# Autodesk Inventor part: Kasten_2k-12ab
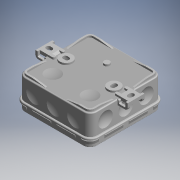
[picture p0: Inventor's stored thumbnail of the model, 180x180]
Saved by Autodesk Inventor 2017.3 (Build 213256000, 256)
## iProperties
Part Number: Kasten_2k-12ab
Material: Generic
Catalog Web Link: www.cadenas.de
Description: Kasten_2k-12ab-Rote Reihe
Vendor: SPELSBERG
Document SubType Name: Modeling
Designer: partserver
Manufacturer: SPELSBERG
Mass: 30.8757 g
Surface Area: 386.027 cm^2
Volume: 30.8757 cm^3
Density: 1 g/cm^3
Appearance: PSOLRGB-215-215-215
Category: PARTsolutions
Company: SPELSBERG
Title: Kasten_2k-12ab
Author: Cadenas PARTsolutions
Comments: Rote Reihe
PSOL_IDENT_0: {$CADENAS_DATA\23d-libs\spelsberg\pool\verbindungsdosen\parts\kasten_2k_12_ab.prj},176 {VTYP=3D},{NB=
PSOL_IDENT_1: Kasten_2k-12ab},{LINA=Kasten_2k-12ab},{NN=Kasten_2k-12ab},{DATE=27.03.2020 09:10:35},{GEOMDATE=05.01
PSOL_IDENT_2: .2015 11:33:00},{VERSION=},{LINEID=10},{WBVAR=},{WBNUMERIC=}  {NB=Kasten_2k-12ab},{LINA=Kasten_2k-12
PSOL_IDENT_3: ab},{KT=DUMMY},{CNSORDERNO=Kasten_2k-12ab}
NB: Kasten_2k-12ab
NN: Kasten_2k-12ab
NT: Rote Reihe
NBSYN: $CNSORDERNO.
LINA: Kasten_2k-12ab
CATALOG: Spelsberg
CNSORDERNO: Kasten_2k-12ab
SUPPLIER: SPELSBERG
ARTICLENO: Kasten_2k-12ab
BOMINFO: Kasten_2k-12ab
CREATOR: CADENAS GmbH
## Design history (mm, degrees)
sketch "Sketch_1"
  geometry: L1 (-40.5, 7.5)-(-40.5, 5); L2 (-40.5, 5)-(-41.411, 1.6); L3 (-41.411, 1.6)-(-40.5, 1.6); L4 (-40.5, 1.6)-(-40.5, 0); L5 (-40.5, 0)-(-42.5, 0); L6 (-42.5, 0)-(-42.5, -1); L7 (-41.5, -2)-(-40.5, -2); L8 (-40.5, -2)-(-40.5, -24.5); L9 (-39.5, -25.5)-(39.5, -25.5); L10 (40.5, -24.5)-(40.5, -2); L11 (40.5, -2)-(41.5, -2); L12 (42.5, -1)-(42.5, 0); L13 (42.5, 0)-(40.5, 0); L14 (40.5, 0)-(40.5, 1.6); L15 (40.5, 1.6)-(41.411, 1.6); L16 (41.411, 1.6)-(40.5, 5); L17 (40.5, 5)-(40.5, 7.5); L18 (40, 8)-(-40, 8); A1 r 0.5 centre (-40, 7.5) between (-40, 8) and (-40.5, 7.5); A2 r 1 centre (-41.5, -1) between (-42.5, -1) and (-41.5, -2); A3 r 1 centre (-39.5, -24.5) between (-40.5, -24.5) and (-39.5, -25.5); A4 r 1 centre (39.5, -24.5) between (39.5, -25.5) and (40.5, -24.5); A5 r 1 centre (41.5, -1) between (41.5, -2) and (42.5, -1); A6 r 0.5 centre (40, 7.5) between (40.5, 7.5) and (40, 8)
  constraints: 36 end point, 12 point on circle, 6 centre point
extrude "Extrusion1" join sketch "Sketch_1" stored distance "d0" = 66; taper "d1" = 0 deg
sketch "Sketch_2"
  geometry: L1 (42.5, 0)-(40.5, 0); L2 (40.5, 0)-(40.5, 1.6); L3 (40.5, 1.6)-(41.411, 1.6); L4 (41.411, 1.6)-(40.5, 5); L5 (40.5, 5)-(40.5, 7.499); L6 (39.999, 8)-(-39.999, 8); L7 (-40.5, 7.499)-(-40.5, 5); L8 (-40.5, 5)-(-41.411, 1.6); L9 (-41.411, 1.6)-(-40.5, 1.6); L10 (-40.5, 1.6)-(-40.5, 0); L11 (-40.5, 0)-(-42.5, 0); L12 (-42.5, 0)-(-42.5, -0.999); L13 (-41.499, -2)-(-40.5, -2); L14 (-40.5, -2)-(-40.5, -24.5); L15 (-39.5, -25.5)-(39.5, -25.5); L16 (40.5, -24.5)-(40.5, -2); L17 (40.5, -2)-(41.499, -2); L18 (42.5, -0.999)-(42.5, 0); A1 r 0.501 centre (39.999, 7.499) between (40.5, 7.499) and (39.999, 8); A2 r 0.501 centre (-39.999, 7.499) between (-39.999, 8) and (-40.5, 7.499); A3 r 1.001 centre (-41.499, -0.999) between (-42.5, -0.999) and (-41.499, -2); A4 r 1 centre (-39.5, -24.5) between (-40.5, -24.5) and (-39.5, -25.5); A5 r 1 centre (39.5, -24.5) between (39.5, -25.5) and (40.5, -24.5); A6 r 1.001 centre (41.499, -0.999) between (41.499, -2) and (42.5, -0.999)
  constraints: 36 end point, 12 point on circle, 6 centre point
extrude "Extrusion2" join sketch "Sketch_2" stored distance "d2" = 66; taper "d3" = 0 deg
sketch "Sketch_7"
  geometry: L1 (-39.5, 10)-(-39.5, 8); L2 (-39, 7.5)-(-39, -24); L3 (-39, -24)-(39, -24); L4 (39, -24)-(39, 7.5); L5 (39.5, 8)-(39.5, 10); L6 (39.5, 10)-(-39.5, 10); A1 r 0.5 centre (-39.5, 7.5) between (-39, 7.5) and (-39.5, 8); A2 r 0.5 centre (39.5, 7.5) between (39.5, 8) and (39, 7.5)
  constraints: 12 end point, 4 point on circle, 2 centre point
extrude "Extrusion3" cut sketch "Sketch_7" stored distance "d4" = 66; taper "d5" = 0 deg
sketch "Sketch_8"
  geometry: L1 (39.5, 8)-(39.5, 10); L2 (39.5, 10)-(-39.5, 10); L3 (-39.5, 10)-(-39.5, 8); L4 (-39, 7.5)-(-39, -24); L5 (-39, -24)-(39, -24); L6 (39, -24)-(39, 7.5); A1 r 0.5 centre (-39.5, 7.5) between (-39, 7.5) and (-39.5, 8); A2 r 0.5 centre (39.5, 7.5) between (39.5, 8) and (39, 7.5)
  constraints: 12 end point, 4 point on circle, 2 centre point
extrude "Extrusion4" cut sketch "Sketch_8" stored distance "d6" = 66; taper "d7" = 0 deg
sketch "Sketch_3"
  geometry: L1 (25.5, 33)-(-8, 33); L2 (24, 33)-(24, 39); L3 (24, 39)-(-7.5, 39); L4 (-8, 39.5)-(-8, 40); L5 (-7.5, 40.5)-(-5, 40.5); L6 (-5, 40.5)-(-1.6, 41.411); L7 (-1.6, 41.411)-(-1.6, 40.5); L8 (-1.6, 40.5)-(0, 40.5); L9 (0, 40.5)-(0, 42.5); L10 (0, 42.5)-(1, 42.5); L11 (2, 41.5)-(2, 40.5); L12 (2, 40.5)-(24.5, 40.5); L13 (25.5, 39.5)-(25.5, 33); L14 (25.5, 33)-(24, 33); A1 r 0.5 centre (-7.5, 39.5) between (-8, 39.5) and (-7.5, 39); A2 r 0.5 centre (-7.5, 40) between (-7.5, 40.5) and (-8, 40); A3 r 1 centre (1, 41.5) between (2, 41.5) and (1, 42.5); A4 r 1 centre (24.5, 39.5) between (25.5, 39.5) and (24.5, 40.5)
  constraints: 28 end point, 8 point on circle, 4 centre point
revolve "Revolution1" sketch "Sketch_3" stored, may be unused: angle "d8" = 90 deg
sketch "Sketch_4"
  geometry: L1 (-8, -33)-(25.5, -33); L2 (25.5, -33)-(25.5, -39.5); L3 (24.5, -40.5)-(2, -40.5); L4 (2, -40.5)-(2, -41.5); L5 (1, -42.5)-(0, -42.5); L6 (0, -42.5)-(0, -40.5); L7 (0, -40.5)-(-1.6, -40.5); L8 (-1.6, -40.5)-(-1.6, -41.411); L9 (-1.6, -41.411)-(-5, -40.5); L10 (-5, -40.5)-(-7.5, -40.5); L11 (-8, -40)-(-8, -39.5); L12 (-7.5, -39)-(24, -39); L13 (24, -39)-(24, -33); L14 (24, -33)-(25.5, -33); A1 r 1 centre (24.5, -39.5) between (24.5, -40.5) and (25.5, -39.5); A2 r 1 centre (1, -41.5) between (1, -42.5) and (2, -41.5); A3 r 0.5 centre (-7.5, -40) between (-8, -40) and (-7.5, -40.5); A4 r 0.5 centre (-7.5, -39.5) between (-7.5, -39) and (-8, -39.5)
  constraints: 28 end point, 8 point on circle, 4 centre point
revolve "Revolution2" sketch "Sketch_4" stored, may be unused: angle "d9" = 90 deg
sketch "Sketch_5"
  geometry: L1 (25.5, 33)-(-8, 33); L2 (24, 33)-(24, 39); L3 (24, 39)-(-7.5, 39); L4 (-8, 39.5)-(-8, 40); L5 (-7.5, 40.5)-(-5, 40.5); L6 (-5, 40.5)-(-1.6, 41.411); L7 (-1.6, 41.411)-(-1.6, 40.5); L8 (-1.6, 40.5)-(0, 40.5); L9 (0, 40.5)-(0, 42.5); L10 (0, 42.5)-(1, 42.5); L11 (2, 41.5)-(2, 40.5); L12 (2, 40.5)-(24.5, 40.5); L13 (25.5, 39.5)-(25.5, 33); L14 (25.5, 33)-(24, 33); A1 r 0.5 centre (-7.5, 39.5) between (-8, 39.5) and (-7.5, 39); A2 r 0.5 centre (-7.5, 40) between (-7.5, 40.5) and (-8, 40); A3 r 1 centre (1, 41.5) between (2, 41.5) and (1, 42.5); A4 r 1 centre (24.5, 39.5) between (25.5, 39.5) and (24.5, 40.5)
  constraints: 28 end point, 8 point on circle, 4 centre point
revolve "Revolution3" sketch "Sketch_5" stored, may be unused: angle "d10" = 90 deg
sketch "Sketch_6"
  geometry: L1 (-8, -33)-(25.5, -33); L2 (25.5, -33)-(25.5, -39.5); L3 (24.5, -40.5)-(2, -40.5); L4 (2, -40.5)-(2, -41.5); L5 (1, -42.5)-(0, -42.5); L6 (0, -42.5)-(0, -40.5); L7 (0, -40.5)-(-1.6, -40.5); L8 (-1.6, -40.5)-(-1.6, -41.411); L9 (-1.6, -41.411)-(-5, -40.5); L10 (-5, -40.5)-(-7.5, -40.5); L11 (-8, -40)-(-8, -39.5); L12 (-7.5, -39)-(24, -39); L13 (24, -39)-(24, -33); L14 (24, -33)-(25.5, -33); A1 r 1 centre (24.5, -39.5) between (24.5, -40.5) and (25.5, -39.5); A2 r 1 centre (1, -41.5) between (1, -42.5) and (2, -41.5); A3 r 0.5 centre (-7.5, -40) between (-8, -40) and (-7.5, -40.5); A4 r 0.5 centre (-7.5, -39.5) between (-7.5, -39) and (-8, -39.5)
  constraints: 28 end point, 8 point on circle, 4 centre point
revolve "Revolution4" sketch "Sketch_6" stored, may be unused: angle "d11" = 90 deg
sketch "Sketch_13"
  geometry: L1 (-27, -19)-(-27, -27.5); L2 (-27, -27.5)-(-34, -27.5); L3 (-34, -27.5)-(-34, -24); L4 (-34, -24)-(-34.087, -24); L5 (-34.087, -24)-(-34, -19); L6 (-34, -19)-(-27, -19); L7 (-27, -19)-(-27, -27.5)
  constraints: 14 end point
revolve "Revolution5" sketch "Sketch_13" stored, may be unused: angle "d12" = 360 deg
sketch "Sketch_16"
  geometry: L1 (27, -19)-(27, -27.5); L2 (27, -27.5)-(20, -27.5); L3 (20, -27.5)-(20, -24); L4 (20, -24)-(19.913, -24); L5 (19.913, -24)-(20, -19); L6 (20, -19)-(27, -19); L7 (27, -19)-(27, -27.5)
  constraints: 14 end point
revolve "Revolution6" sketch "Sketch_16" stored, may be unused: angle "d13" = 360 deg
sketch "Sketch_14"
  geometry: L1 (-27, -19)-(-27, -26); L2 (-27, -26)-(-32.4, -26); L3 (-32.4, -26)-(-32.505, -20); L4 (-32.505, -20)-(-33.505, -19); L5 (-33.505, -19)-(-27, -19); L6 (-27, -19)-(-27, -26)
  constraints: 12 end point
revolve "Revolution7" sketch "Sketch_14" stored, may be unused: angle "d14" = 360 deg
sketch "Sketch_15"
  geometry: L1 (27, -19)-(27, -26); L2 (27, -26)-(21.6, -26); L3 (21.6, -26)-(21.495, -20); L4 (21.495, -20)-(20.495, -19); L5 (20.495, -19)-(27, -19); L6 (27, -19)-(27, -26)
  constraints: 12 end point
revolve "Revolution8" sketch "Sketch_15" stored, may be unused: angle "d15" = 360 deg
sketch "Sketch_17"
  geometry: L1 (26, -2.5)-(28, -2.5); L2 (28, 2.5)-(26, 2.5); A1 r 2.5 centre (26, 0) between (26, 2.5) and (26, -2.5); A2 r 2.5 centre (28, 0) between (28, -2.5) and (28, 2.5)
  constraints: 4 end point, 4 point on circle, 2 centre point
extrude "Extrusion5" cut sketch "Sketch_17" distance "d16" = 1.5; taper "d17" = 0 deg
sketch "Sketch_18"
  geometry: L1 (-24.5, -1)-(-24.5, 1); L2 (-29.5, 1)-(-29.5, -1); A1 r 2.5 centre (-27, -1) between (-29.5, -1) and (-24.5, -1); A2 r 2.5 centre (-27, 1) between (-24.5, 1) and (-29.5, 1)
  constraints: 4 end point, 4 point on circle, 2 centre point
extrude "Extrusion6" cut sketch "Sketch_18" distance "d18" = 1.5; taper "d19" = 0 deg
sketch "Sketch_19"
  geometry: L1 (0, -18)-(0, -24); L2 (-3.698, -24)-(-3.75, -18); L3 (-3.75, -18)-(-4.5, -18); L4 (-4.5, -18)-(-5, -18.5); L5 (-5, -18.5)-(-5, -24); L6 (-5, -24)-(-3.698, -24)
  constraints: 12 end point
revolve "Revolution9" sketch "Sketch_19" stored, may be unused: angle "d20" = 360 deg
sketch "Sketch_20"
  geometry: L1 (19, -27.5)-(19, -18); L2 (19, -18)-(21.7, -18); L3 (21.7, -18)-(21.805, -24); L4 (21.805, -24)-(22.2, -24); L5 (22.2, -24)-(22.2, -27.5); L6 (22.2, -27.5)-(19, -27.5); L7 (19, -27.5)-(19, -18)
  constraints: 14 end point
revolve "Revolution10" sketch "Sketch_20" stored, may be unused: angle "d21" = 360 deg
sketch "Sketch_21"
  geometry: L1 (-4.964, 18.4)-(-0.6, 18.4); L2 (-0.6, 18.4)-(-0.6, 14.036); L3 (0.6, 14.036)-(0.6, 18.4); L4 (0.6, 18.4)-(4.964, 18.4); L5 (4.964, 19.6)-(0.6, 19.6); L6 (0.6, 19.6)-(0.6, 23.964); L7 (-0.6, 23.964)-(-0.6, 19.6); L8 (-0.6, 19.6)-(-4.964, 19.6); A1 r 5 centre (0, 19) between (-4.964, 19.6) and (-4.964, 18.4); A2 r 5 centre (0, 19) between (-0.6, 14.036) and (0.6, 14.036); A3 r 5 centre (0, 19) between (4.964, 18.4) and (4.964, 19.6); A4 r 5 centre (0, 19) between (0.6, 23.964) and (-0.6, 23.964)
  constraints: 16 end point, 8 point on circle, 4 centre point
extrude "Extrusion7" join sketch "Sketch_21" distance "d22" = 6; taper "d23" = 0 deg
sketch "Sketch_22"
  geometry: L1 (19, -26.5)-(19, -18); L2 (19, -18)-(21, -18); L3 (21, -18)-(21, -19); L4 (21, -19)-(20.7, -19); L5 (20.7, -19)-(20.635, -26.5); L6 (20.635, -26.5)-(19, -26.5); L7 (19, -26.5)-(19, -18)
  constraints: 14 end point
revolve "Revolution11" sketch "Sketch_22" stored, may be unused: angle "d24" = 360 deg
sketch "Sketch_23"
  geometry: L1 (1.7, -24)-(3.301, -24); L2 (12.83, -32.749)-(24, -32.943); L3 (24, -32.943)-(24, 32.943); L4 (24, 32.943)-(12.83, 32.749); L5 (3.301, 24)-(1.7, 24); L6 (1.7, 24)-(1.7, 22); L7 (1.7, 22)-(3.301, 22); L8 (12.83, 13.251)-(21.5, 13.1); L9 (21.5, 13.1)-(21.5, 9.9); L10 (21.5, 9.9)-(12.83, 9.749); L11 (3.301, 1)-(1.7, 1); L12 (1.7, 1)-(1.7, -1); L13 (1.7, -1)-(3.301, -1); L14 (12.83, -9.749)-(21.5, -9.9); L15 (21.5, -9.9)-(21.5, -13.1); L16 (21.5, -13.1)-(12.83, -13.251); L17 (3.301, -22)-(1.7, -22); L18 (1.7, -22)-(1.7, -24); A1 r 9.75 centre (13, -23) between (3.301, -24) and (12.83, -32.749); A2 r 9.75 centre (13, 23) between (12.83, 32.749) and (3.301, 24); A3 r 9.75 centre (13, 23) between (3.301, 22) and (12.83, 13.251); A4 r 9.75 centre (13, 0) between (12.83, 9.749) and (3.301, 1); A5 r 9.75 centre (13, 0) between (3.301, -1) and (12.83, -9.749); A6 r 9.75 centre (13, -23) between (12.83, -13.251) and (3.301, -22)
  constraints: 36 end point, 12 point on circle, 6 centre point
extrude "Extrusion8" join sketch "Sketch_23" distance "d25" = 1; taper "d26" = 0 deg
sketch "Sketch_24"
  geometry: L1 (1.7, -24)-(3.301, -24); L2 (12.83, -32.749)-(24, -32.943); L3 (24, -32.943)-(24, 32.943); L4 (24, 32.943)-(12.83, 32.749); L5 (3.301, 24)-(1.7, 24); L6 (1.7, 24)-(1.7, 22); L7 (1.7, 22)-(3.301, 22); L8 (12.83, 13.251)-(21.5, 13.1); L9 (21.5, 13.1)-(21.5, 9.9); L10 (21.5, 9.9)-(12.83, 9.749); L11 (3.301, 1)-(1.7, 1); L12 (1.7, 1)-(1.7, -1); L13 (1.7, -1)-(3.301, -1); L14 (12.83, -9.749)-(21.5, -9.9); L15 (21.5, -9.9)-(21.5, -13.1); L16 (21.5, -13.1)-(12.83, -13.251); L17 (3.301, -22)-(1.7, -22); L18 (1.7, -22)-(1.7, -24); A1 r 9.75 centre (13, -23) between (3.301, -24) and (12.83, -32.749); A2 r 9.75 centre (13, 23) between (12.83, 32.749) and (3.301, 24); A3 r 9.75 centre (13, 23) between (3.301, 22) and (12.83, 13.251); A4 r 9.75 centre (13, 0) between (12.83, 9.749) and (3.301, 1); A5 r 9.75 centre (13, 0) between (3.301, -1) and (12.83, -9.749); A6 r 9.75 centre (13, -23) between (12.83, -13.251) and (3.301, -22)
  constraints: 36 end point, 12 point on circle, 6 centre point
extrude "Extrusion9" join sketch "Sketch_24" distance "d27" = 1; taper "d28" = 0 deg
sketch "Sketch_25"
  geometry: L1 (-32.943, 24)-(-32.749, 12.83); L2 (-24, 3.301)-(-24, 1.7); L3 (-24, 1.7)-(-22, 1.7); L4 (-22, 1.7)-(-22, 3.301); L5 (-13.251, 12.83)-(-13.1, 21.5); L6 (-13.1, 21.5)-(-9.9, 21.5); L7 (-9.9, 21.5)-(-9.749, 12.83); L8 (-1, 3.301)-(-1, 1.7); L9 (-1, 1.7)-(1, 1.7); L10 (1, 1.7)-(1, 3.301); L11 (9.749, 12.83)-(9.9, 21.5); L12 (9.9, 21.5)-(13.1, 21.5); L13 (13.1, 21.5)-(13.251, 12.83); L14 (22, 3.301)-(22, 1.7); L15 (22, 1.7)-(24, 1.7); L16 (24, 1.7)-(24, 3.301); L17 (32.749, 12.83)-(32.943, 24); L18 (32.943, 24)-(-32.943, 24); A1 r 9.75 centre (-23, 13) between (-32.749, 12.83) and (-24, 3.301); A2 r 9.75 centre (-23, 13) between (-22, 3.301) and (-13.251, 12.83); A3 r 9.75 centre (0, 13) between (-9.749, 12.83) and (-1, 3.301); A4 r 9.75 centre (0, 13) between (1, 3.301) and (9.749, 12.83); A5 r 9.75 centre (23, 13) between (13.251, 12.83) and (22, 3.301); A6 r 9.75 centre (23, 13) between (24, 3.301) and (32.749, 12.83)
  constraints: 36 end point, 12 point on circle, 6 centre point
extrude "Extrusion10" join sketch "Sketch_25" distance "d29" = 1; taper "d30" = 0 deg
sketch "Sketch_26"
  geometry: L1 (-32.943, 24)-(-32.749, 12.83); L2 (-24, 3.301)-(-24, 1.7); L3 (-24, 1.7)-(-22, 1.7); L4 (-22, 1.7)-(-22, 3.301); L5 (-13.251, 12.83)-(-13.1, 21.5); L6 (-13.1, 21.5)-(-9.9, 21.5); L7 (-9.9, 21.5)-(-9.749, 12.83); L8 (-1, 3.301)-(-1, 1.7); L9 (-1, 1.7)-(1, 1.7); L10 (1, 1.7)-(1, 3.301); L11 (9.749, 12.83)-(9.9, 21.5); L12 (9.9, 21.5)-(13.1, 21.5); L13 (13.1, 21.5)-(13.251, 12.83); L14 (22, 3.301)-(22, 1.7); L15 (22, 1.7)-(24, 1.7); L16 (24, 1.7)-(24, 3.301); L17 (32.749, 12.83)-(32.943, 24); L18 (32.943, 24)-(-32.943, 24); A1 r 9.75 centre (-23, 13) between (-32.749, 12.83) and (-24, 3.301); A2 r 9.75 centre (-23, 13) between (-22, 3.301) and (-13.251, 12.83); A3 r 9.75 centre (0, 13) between (-9.749, 12.83) and (-1, 3.301); A4 r 9.75 centre (0, 13) between (1, 3.301) and (9.749, 12.83); A5 r 9.75 centre (23, 13) between (13.251, 12.83) and (22, 3.301); A6 r 9.75 centre (23, 13) between (24, 3.301) and (32.749, 12.83)
  constraints: 36 end point, 12 point on circle, 6 centre point
extrude "Extrusion11" join sketch "Sketch_26" distance "d31" = 1; taper "d32" = 0 deg
sketch "Sketch_27"
  geometry: L1 (-23, -40.5)-(-23, -38.559); L2 (-14.75, -40.5)-(-23, -40.5); L3 (-23, -40.5)-(-23, -38.559); A1 r 18.5 centre (-22.999, -57.059) between (-14.75, -40.5) and (-23, -38.559)
  constraints: 6 end point, 2 point on circle, 1 centre point
revolve "Revolution12" sketch "Sketch_27" stored, may be unused: angle "d33" = 360 deg
sketch "Sketch_28"
  geometry: L1 (0, -40.5)-(0, -38.559); L2 (8.25, -40.5)-(0, -40.5); L3 (0, -40.5)-(0, -38.559); A1 r 18.5 centre (0.001, -57.059) between (8.25, -40.5) and (0, -38.559)
  constraints: 6 end point, 2 point on circle, 1 centre point
revolve "Revolution13" sketch "Sketch_28" stored, may be unused: angle "d34" = 360 deg
sketch "Sketch_29"
  geometry: L1 (23, -40.5)-(23, -38.559); L2 (31.25, -40.5)-(23, -40.5); L3 (23, -40.5)-(23, -38.559); A1 r 18.5 centre (23.001, -57.059) between (31.25, -40.5) and (23, -38.559)
  constraints: 6 end point, 2 point on circle, 1 centre point
revolve "Revolution14" sketch "Sketch_29" stored, may be unused: angle "d35" = 360 deg
sketch "Sketch_30"
  geometry: L1 (23, 38.559)-(23, 40.5); L2 (23, 40.5)-(31.25, 40.5); L3 (23, 38.559)-(23, 40.5); A1 r 18.5 centre (23.001, 57.059) between (23, 38.559) and (31.25, 40.5)
  constraints: 6 end point, 2 point on circle, 1 centre point
revolve "Revolution15" sketch "Sketch_30" stored, may be unused: angle "d36" = 360 deg
sketch "Sketch_31"
  geometry: L1 (0, 38.559)-(0, 40.5); L2 (0, 40.5)-(8.25, 40.5); L3 (0, 38.559)-(0, 40.5); A1 r 18.5 centre (0.001, 57.059) between (0, 38.559) and (8.25, 40.5)
  constraints: 6 end point, 2 point on circle, 1 centre point
revolve "Revolution16" sketch "Sketch_31" stored, may be unused: angle "d37" = 360 deg
sketch "Sketch_32"
  geometry: L1 (-23, 38.559)-(-23, 40.5); L2 (-23, 40.5)-(-14.75, 40.5); L3 (-23, 38.559)-(-23, 40.5); A1 r 18.5 centre (-22.999, 57.059) between (-23, 38.559) and (-14.75, 40.5)
  constraints: 6 end point, 2 point on circle, 1 centre point
revolve "Revolution17" sketch "Sketch_32" stored, may be unused: angle "d38" = 360 deg
sketch "Sketch_33"
  geometry: L1 (40.5, 23)-(38.559, 23); L2 (40.5, 31.25)-(40.5, 23); L3 (40.5, 23)-(38.559, 23); A1 r 18.5 centre (57.059, 23.001) between (40.5, 31.25) and (38.559, 23)
  constraints: 6 end point, 2 point on circle, 1 centre point
revolve "Revolution18" sketch "Sketch_33" stored, may be unused: angle "d39" = 360 deg
sketch "Sketch_34"
  geometry: L1 (40.5, 0)-(38.559, 0); L2 (40.5, 8.25)-(40.5, 0); L3 (40.5, 0)-(38.559, 0); A1 r 18.5 centre (57.059, 0.001) between (40.5, 8.25) and (38.559, 0)
  constraints: 6 end point, 2 point on circle, 1 centre point
revolve "Revolution19" sketch "Sketch_34" stored, may be unused: angle "d40" = 360 deg
sketch "Sketch_35"
  geometry: L1 (40.5, -23)-(38.559, -23); L2 (40.5, -14.75)-(40.5, -23); L3 (40.5, -23)-(38.559, -23); A1 r 18.5 centre (57.059, -22.999) between (40.5, -14.75) and (38.559, -23)
  constraints: 6 end point, 2 point on circle, 1 centre point
revolve "Revolution20" sketch "Sketch_35" stored, may be unused: angle "d41" = 360 deg
sketch "Sketch_36"
  geometry: L1 (-38.559, 23)-(-40.5, 23); L2 (-40.5, 23)-(-40.5, 31.25); L3 (-38.559, 23)-(-40.5, 23); A1 r 18.5 centre (-57.059, 23.001) between (-38.559, 23) and (-40.5, 31.25)
  constraints: 6 end point, 2 point on circle, 1 centre point
revolve "Revolution21" sketch "Sketch_36" stored, may be unused: angle "d42" = 360 deg
sketch "Sketch_37"
  geometry: L1 (-38.559, 0)-(-40.5, 0); L2 (-40.5, 0)-(-40.5, 8.25); L3 (-38.559, 0)-(-40.5, 0); A1 r 18.5 centre (-57.059, 0.001) between (-38.559, 0) and (-40.5, 8.25)
  constraints: 6 end point, 2 point on circle, 1 centre point
revolve "Revolution22" sketch "Sketch_37" stored, may be unused: angle "d43" = 360 deg
sketch "Sketch_38"
  geometry: L1 (-38.559, -23)-(-40.5, -23); L2 (-40.5, -23)-(-40.5, -14.75); L3 (-38.559, -23)-(-40.5, -23); A1 r 18.5 centre (-57.059, -22.999) between (-38.559, -23) and (-40.5, -14.75)
  constraints: 6 end point, 2 point on circle, 1 centre point
revolve "Revolution23" sketch "Sketch_38" stored, may be unused: angle "d44" = 360 deg
sketch "Sketch_51"
  geometry: L1 (-45, -45)-(45, -45); L2 (45, -45)-(45, 45); L3 (45, 45)-(-45, 45); L4 (-45, 45)-(-45, -45); L5 (-41.914, -31.914)-(-41.914, -41.914); L6 (-41.914, -41.914)-(-31.914, -41.914); L7 (-31.914, -41.914)-(-30.5, -40.5); L8 (-30.5, -40.5)-(-24.5, -40.5); L9 (-24.5, -40.5)-(-23.086, -41.914); L10 (-23.086, -41.914)-(-4.414, -41.914); L11 (-4.414, -41.914)-(-3, -40.5); L12 (-3, -40.5)-(3, -40.5); L13 (3, -40.5)-(4.414, -41.914); L14 (4.414, -41.914)-(23.086, -41.914); L15 (23.086, -41.914)-(24.5, -40.5); L16 (24.5, -40.5)-(30.5, -40.5); L17 (30.5, -40.5)-(31.914, -41.914); L18 (31.914, -41.914)-(41.914, -41.914); L19 (41.914, -41.914)-(41.914, -31.914); L20 (41.914, -31.914)-(40.5, -30.5); L21 (40.5, -30.5)-(40.5, -24.5); L22 (40.5, -24.5)-(41.914, -23.086); L23 (41.914, -23.086)-(41.914, -4.414); L24 (41.914, -4.414)-(40.5, -3); L25 (40.5, -3)-(40.5, 3); L26 (40.5, 3)-(41.914, 4.414); L27 (41.914, 4.414)-(41.914, 23.086); L28 (41.914, 23.086)-(40.5, 24.5); L29 (40.5, 24.5)-(40.5, 30.5); L30 (40.5, 30.5)-(41.914, 31.914); L31 (41.914, 31.914)-(41.914, 41.914); L32 (41.914, 41.914)-(31.914, 41.914); L33 (31.914, 41.914)-(30.5, 40.5); L34 (30.5, 40.5)-(24.5, 40.5); L35 (24.5, 40.5)-(23.086, 41.914); L36 (23.086, 41.914)-(4.414, 41.914); L37 (4.414, 41.914)-(3, 40.5); L38 (3, 40.5)-(-3, 40.5); L39 (-3, 40.5)-(-4.414, 41.914); L40 (-4.414, 41.914)-(-23.086, 41.914); L41 (-23.086, 41.914)-(-24.5, 40.5); L42 (-24.5, 40.5)-(-30.5, 40.5); L43 (-30.5, 40.5)-(-31.914, 41.914); L44 (-31.914, 41.914)-(-41.914, 41.914); L45 (-41.914, 41.914)-(-41.914, 31.914); L46 (-41.914, 31.914)-(-40.5, 30.5); L47 (-40.5, 30.5)-(-40.5, 24.5); L48 (-40.5, 24.5)-(-41.914, 23.086); L49 (-41.914, 23.086)-(-41.914, 4.414); L50 (-41.914, 4.414)-(-40.5, 3); L51 (-40.5, 3)-(-40.5, -3); L52 (-40.5, -3)-(-41.914, -4.414); L53 (-41.914, -4.414)-(-41.914, -23.086); L54 (-41.914, -23.086)-(-40.5, -24.5); L55 (-40.5, -24.5)-(-40.5, -30.5); L56 (-40.5, -30.5)-(-41.914, -31.914)
  constraints: 112 end point
extrude "Extrusion12" cut sketch "Sketch_51" distance "d45" = 3.4; taper "d46" = 0 deg
sketch "Sketch_52"
  geometry: L1 (11.5, 36.5)-(33, 36.5); L2 (36.5, 33)-(36.5, 11.5); L3 (36.5, 11.5)-(38.5, 11.5); L4 (38.5, 11.5)-(38.5, 33); L5 (33, 38.5)-(11.5, 38.5); L6 (11.5, 38.5)-(11.5, 36.5); A1 r 3.5 centre (33, 33) between (36.5, 33) and (33, 36.5); A2 r 5.5 centre (33, 33) between (38.5, 33) and (33, 38.5)
  constraints: 12 end point, 4 point on circle, 2 centre point
extrude "Extrusion13" join sketch "Sketch_52" distance "d47" = 2; taper "d48" = 0 deg
sketch "Sketch_53"
  geometry: L1 (-38.5, 33)-(-38.5, 11.5); L2 (-38.5, 11.5)-(-36.5, 11.5); L3 (-36.5, 11.5)-(-36.5, 33); L4 (-33, 36.5)-(-11.5, 36.5); L5 (-11.5, 36.5)-(-11.5, 38.5); L6 (-11.5, 38.5)-(-33, 38.5); A1 r 3.5 centre (-33, 33) between (-33, 36.5) and (-36.5, 33); A2 r 5.5 centre (-33, 33) between (-33, 38.5) and (-38.5, 33)
  constraints: 12 end point, 4 point on circle, 2 centre point
extrude "Extrusion14" join sketch "Sketch_53" distance "d49" = 2; taper "d50" = 0 deg
sketch "Sketch_54"
  geometry: L1 (11.5, -36.5)-(11.5, -38.5); L2 (11.5, -38.5)-(33, -38.5); L3 (38.5, -33)-(38.5, -11.5); L4 (38.5, -11.5)-(36.5, -11.5); L5 (36.5, -11.5)-(36.5, -33); L6 (33, -36.5)-(11.5, -36.5); A1 r 5.5 centre (33, -33) between (33, -38.5) and (38.5, -33); A2 r 3.5 centre (33, -33) between (33, -36.5) and (36.5, -33)
  constraints: 12 end point, 4 point on circle, 2 centre point
extrude "Extrusion15" join sketch "Sketch_54" distance "d51" = 2; taper "d52" = 0 deg
sketch "Sketch_55"
  geometry: L1 (-33, -38.5)-(-11.5, -38.5); L2 (-11.5, -38.5)-(-11.5, -36.5); L3 (-11.5, -36.5)-(-33, -36.5); L4 (-36.5, -33)-(-36.5, -11.5); L5 (-36.5, -11.5)-(-38.5, -11.5); L6 (-38.5, -11.5)-(-38.5, -33); A1 r 5.5 centre (-33, -33) between (-38.5, -33) and (-33, -38.5); A2 r 3.5 centre (-33, -33) between (-36.5, -33) and (-33, -36.5)
  constraints: 12 end point, 4 point on circle, 2 centre point
extrude "Extrusion16" join sketch "Sketch_55" distance "d53" = 2; taper "d54" = 0 deg
sketch "Sketch_56"
  geometry: L1 (-26, 27.5)-(-11.769, 25.5); L2 (-11.769, 25.5)-(11.769, 25.5); L3 (11.769, 25.5)-(26, 27.5); L4 (26, 27.5)-(-26, 27.5)
  constraints: 8 end point
extrude "Extrusion17" cut sketch "Sketch_56" distance "d55" = 2; taper "d56" = 0 deg
sketch "Sketch_57"
  geometry: L1 (-26, 27.5)-(-11.769, 25.5); L2 (-11.769, 25.5)-(11.769, 25.5); L3 (11.769, 25.5)-(26, 27.5); L4 (26, 27.5)-(-26, 27.5)
  constraints: 8 end point
extrude "Extrusion18" cut sketch "Sketch_57" distance "d57" = 2; taper "d58" = 0 deg
sketch "Sketch_58"
  geometry: L1 (25.5, 11.769)-(25.5, -11.769); L2 (25.5, -11.769)-(27.5, -26); L3 (27.5, -26)-(27.5, 26); L4 (27.5, 26)-(25.5, 11.769)
  constraints: 8 end point
extrude "Extrusion19" cut sketch "Sketch_58" distance "d59" = 2; taper "d60" = 0 deg
sketch "Sketch_59"
  geometry: L1 (25.5, 11.769)-(25.5, -11.769); L2 (25.5, -11.769)-(27.5, -26); L3 (27.5, -26)-(27.5, 26); L4 (27.5, 26)-(25.5, 11.769)
  constraints: 8 end point
extrude "Extrusion20" cut sketch "Sketch_59" distance "d61" = 2; taper "d62" = 0 deg
sketch "Sketch_61"
  geometry: L1 (-37, -25.5)-(-37, -24); L2 (-37, -24)-(-52, -24); L3 (-52, -24)-(-52, -27.5); L4 (-52, -27.5)-(-39, -27.5); L5 (-39, -27.5)-(-37, -25.5)
  constraints: 10 end point
extrude "Extrusion21" join sketch "Sketch_61" stored distance "d63" = 14; taper "d64" = 0 deg
sketch "Sketch_63"
  geometry: L1 (52, -24)-(37, -24); L2 (37, -24)-(37, -25.5); L3 (37, -25.5)-(39, -27.5); L4 (39, -27.5)-(52, -27.5); L5 (52, -27.5)-(52, -24)
  constraints: 10 end point
extrude "Extrusion22" join sketch "Sketch_63" stored distance "d65" = 14; taper "d66" = 0 deg
sketch "Sketch_62"
  geometry: L1 (39.5, 25.5)-(39.5, 20); L2 (39.5, 20)-(49, 20); L3 (52, 23)-(52, 27.5); L4 (52, 27.5)-(49.5, 27.5); L5 (49.5, 27.5)-(49.5, 23); L6 (48.5, 22)-(43, 22); L7 (42, 23)-(42, 24.5); L8 (41, 25.5)-(39.5, 25.5); A1 r 3 centre (49, 23) between (49, 20) and (52, 23); A2 r 1 centre (48.5, 23) between (48.5, 22) and (49.5, 23); A3 r 1 centre (43, 23) between (42, 23) and (43, 22); A4 r 1 centre (41, 24.5) between (42, 24.5) and (41, 25.5)
  constraints: 16 end point, 8 point on circle, 4 centre point
extrude "Extrusion23" join sketch "Sketch_62" distance "d67" = 2.5; taper "d68" = 0 deg
sketch "Sketch_64"
  geometry: L1 (-52, 27.5)-(-52, 23); L2 (-49, 20)-(-39.5, 20); L3 (-39.5, 20)-(-39.5, 25.5); L4 (-39.5, 25.5)-(-41, 25.5); L5 (-42, 24.5)-(-42, 23); L6 (-43, 22)-(-48.5, 22); L7 (-49.5, 23)-(-49.5, 27.5); L8 (-49.5, 27.5)-(-52, 27.5); A1 r 3 centre (-49, 23) between (-52, 23) and (-49, 20); A2 r 1 centre (-41, 24.5) between (-41, 25.5) and (-42, 24.5); A3 r 1 centre (-43, 23) between (-43, 22) and (-42, 23); A4 r 1 centre (-48.5, 23) between (-49.5, 23) and (-48.5, 22)
  constraints: 16 end point, 8 point on circle, 4 centre point
extrude "Extrusion24" join sketch "Sketch_64" distance "d69" = 2.5; taper "d70" = 0 deg
sketch "Sketch_65"
  geometry: L1 (39.5, 25.5)-(39.5, 20); L2 (39.5, 20)-(49, 20); L3 (52, 23)-(52, 27.5); L4 (52, 27.5)-(49.5, 27.5); L5 (49.5, 27.5)-(49.5, 23); L6 (48.5, 22)-(43, 22); L7 (42, 23)-(42, 24.5); L8 (41, 25.5)-(39.5, 25.5); A1 r 3 centre (49, 23) between (49, 20) and (52, 23); A2 r 1 centre (48.5, 23) between (48.5, 22) and (49.5, 23); A3 r 1 centre (43, 23) between (42, 23) and (43, 22); A4 r 1 centre (41, 24.5) between (42, 24.5) and (41, 25.5)
  constraints: 16 end point, 8 point on circle, 4 centre point
extrude "Extrusion25" join sketch "Sketch_65" distance "d71" = 2.5; taper "d72" = 0 deg
sketch "Sketch_66"
  geometry: L1 (-52, 27.5)-(-52, 23); L2 (-49, 20)-(-39.5, 20); L3 (-39.5, 20)-(-39.5, 25.5); L4 (-39.5, 25.5)-(-41, 25.5); L5 (-42, 24.5)-(-42, 23); L6 (-43, 22)-(-48.5, 22); L7 (-49.5, 23)-(-49.5, 27.5); L8 (-49.5, 27.5)-(-52, 27.5); A1 r 3 centre (-49, 23) between (-52, 23) and (-49, 20); A2 r 1 centre (-41, 24.5) between (-41, 25.5) and (-42, 24.5); A3 r 1 centre (-43, 23) between (-43, 22) and (-42, 23); A4 r 1 centre (-48.5, 23) between (-49.5, 23) and (-48.5, 22)
  constraints: 16 end point, 8 point on circle, 4 centre point
extrude "Extrusion26" join sketch "Sketch_66" distance "d73" = 2.5; taper "d74" = 0 deg
sketch "Sketch_67"
  geometry: L1 (45, -2.5)-(47, -2.5); L2 (47, 2.5)-(45, 2.5); A1 r 2.5 centre (45, 0) between (45, 2.5) and (45, -2.5); A2 r 2.5 centre (47, 0) between (47, -2.5) and (47, 2.5)
  constraints: 4 end point, 4 point on circle, 2 centre point
extrude "Extrusion27" cut sketch "Sketch_67" distance "d75" = 3.5; taper "d76" = 0 deg
sketch "Sketch_68"
  geometry: L1 (-43.5, -1)-(-43.5, 1); L2 (-48.5, 1)-(-48.5, -1); A1 r 2.5 centre (-46, -1) between (-48.5, -1) and (-43.5, -1); A2 r 2.5 centre (-46, 1) between (-43.5, 1) and (-48.5, 1)
  constraints: 4 end point, 4 point on circle, 2 centre point
extrude "Extrusion28" cut sketch "Sketch_68" distance "d77" = 3.5; taper "d78" = 0 deg
sketch "Sketch_72"
  geometry: L1 (20, -29.189)-(20, -37.6); L2 (20, -37.6)-(22, -37.6); L3 (22, -37.6)-(22, -29.189); A1 r 8.25 centre (21, -21) between (22, -29.189) and (20, -29.189)
  constraints: 6 end point, 2 point on circle, 1 centre point
extrude "Extrusion29" cut sketch "Sketch_72" distance "d79" = 1.5; taper "d80" = 0 deg
sketch "Sketch_69"
  geometry: L1 (-37.6, -22)-(-29.189, -22); L2 (-29.189, -20)-(-37.6, -20); L3 (-37.6, -20)-(-37.6, -22); A1 r 8.25 centre (-21, -21) between (-29.189, -22) and (-29.189, -20)
  constraints: 6 end point, 2 point on circle, 1 centre point
extrude "Extrusion30" cut sketch "Sketch_69" distance "d81" = 1.5; taper "d82" = 0 deg
sketch "Sketch_70"
  geometry: L1 (20, -29.189)-(20, -37.6); L2 (20, -37.6)-(22, -37.6); L3 (22, -37.6)-(22, -29.189); A1 r 8.25 centre (21, -21) between (22, -29.189) and (20, -29.189)
  constraints: 6 end point, 2 point on circle, 1 centre point
extrude "Extrusion31" join sketch "Sketch_70" distance "d83" = 1.5; taper "d84" = 0 deg
sketch "Sketch_73"
  geometry: L1 (-37.6, -22)-(-29.189, -22); L2 (-29.189, -20)-(-37.6, -20); L3 (-37.6, -20)-(-37.6, -22); A1 r 8.25 centre (-21, -21) between (-29.189, -22) and (-29.189, -20)
  constraints: 6 end point, 2 point on circle, 1 centre point
extrude "Extrusion32" join sketch "Sketch_73" distance "d85" = 1.5; taper "d86" = 0 deg
sketch "Sketch_75"
  geometry: L1 (21, 20)-(37.6, 20); L2 (37.6, 20)-(37.6, 22); L3 (37.6, 22)-(21, 22); A1 r 1 centre (21, 21) between (21, 22) and (21, 20)
  constraints: 6 end point, 2 point on circle, 1 centre point
extrude "Extrusion33" cut sketch "Sketch_75" distance "d87" = 1.5; taper "d88" = 0 deg
sketch "Sketch_76"
  geometry: L1 (21, 20)-(37.6, 20); L2 (37.6, 20)-(37.6, 22); L3 (37.6, 22)-(21, 22); A1 r 1 centre (21, 21) between (21, 22) and (21, 20)
  constraints: 6 end point, 2 point on circle, 1 centre point
extrude "Extrusion34" join sketch "Sketch_76" distance "d89" = 1.5; taper "d90" = 0 deg
sketch "Sketch_77"
  geometry: L1 (-22, 37.6)-(-22, 21); L2 (-20, 21)-(-20, 37.6); L3 (-20, 37.6)-(-22, 37.6); A1 r 1 centre (-21, 21) between (-22, 21) and (-20, 21)
  constraints: 6 end point, 2 point on circle, 1 centre point
extrude "Extrusion35" cut sketch "Sketch_77" distance "d91" = 1.5; taper "d92" = 0 deg
sketch "Sketch_78"
  geometry: L1 (-22, 37.6)-(-22, 21); L2 (-20, 21)-(-20, 37.6); L3 (-20, 37.6)-(-22, 37.6); A1 r 1 centre (-21, 21) between (-22, 21) and (-20, 21)
  constraints: 6 end point, 2 point on circle, 1 centre point
extrude "Extrusion36" join sketch "Sketch_78" distance "d93" = 1.5; taper "d94" = 0 deg
sketch "Sketch_71"
  geometry: L1 (21, 25.5)-(21, 24.343); L2 (12.75, 25.5)-(21, 25.5); L3 (21, 25.5)-(21, 24.343); A1 r 30 centre (21.001, 54.343) between (12.75, 25.5) and (21, 24.343)
  constraints: 6 end point, 2 point on circle, 1 centre point
revolve "Revolution24" sketch "Sketch_71" stored, may be unused: angle "d95" = 360 deg
sketch "Sketch_74"
  geometry: L1 (-21, 25.5)-(-21, 24.343); L2 (-29.25, 25.5)-(-21, 25.5); L3 (-21, 25.5)-(-21, 24.343); A1 r 30 centre (-20.999, 54.343) between (-29.25, 25.5) and (-21, 24.343)
  constraints: 6 end point, 2 point on circle, 1 centre point
revolve "Revolution25" sketch "Sketch_74" stored, may be unused: angle "d96" = 360 deg
sketch "Sketch_79"
  geometry: L1 (25, 33)-(24, 33); L2 (24, 33)-(24, 35.5); L3 (24, 35.5)-(25, 35.5); L4 (25, 35.5)-(25, 33); L5 (25, 33)-(24, 33)
  constraints: 10 end point
revolve "Revolution26" sketch "Sketch_79" stored, may be unused: angle "d97" = 360 deg
sketch "Sketch_80"
  geometry: L1 (25, -33)-(24, -33); L2 (24, -33)-(24, -30.5); L3 (24, -30.5)-(25, -30.5); L4 (25, -30.5)-(25, -33); L5 (25, -33)-(24, -33)
  constraints: 10 end point
revolve "Revolution27" sketch "Sketch_80" stored, may be unused: angle "d98" = 360 deg
sketch "Sketch_81"
  geometry: L1 (35.625, -7)-(40, -7); L2 (40, -7)-(40, 7); L3 (40, 7)-(35.625, 7); L4 (35.625, 3.75)-(39.5, 3.75); L5 (39.5, 3.75)-(39.5, -3.75); L6 (39.5, -3.75)-(35.625, -3.75); A1 r 1.625 centre (35.625, -5.375) between (35.625, -3.75) and (35.625, -7); A2 r 1.625 centre (35.625, 5.375) between (35.625, 7) and (35.625, 3.75)
  constraints: 12 end point, 4 point on circle, 2 centre point
extrude "Extrusion37" join sketch "Sketch_81" distance "d99" = 2; taper "d100" = 0 deg
sketch "Sketch_82"
  geometry: L1 (-40, -7)-(-35.625, -7); L2 (-35.625, -3.75)-(-39.5, -3.75); L3 (-39.5, -3.75)-(-39.5, 3.75); L4 (-39.5, 3.75)-(-35.625, 3.75); L5 (-35.625, 7)-(-40, 7); L6 (-40, 7)-(-40, -7); A1 r 1.625 centre (-35.625, -5.375) between (-35.625, -7) and (-35.625, -3.75); A2 r 1.625 centre (-35.625, 5.375) between (-35.625, 3.75) and (-35.625, 7)
  constraints: 12 end point, 4 point on circle, 2 centre point
extrude "Extrusion38" join sketch "Sketch_82" distance "d101" = 2; taper "d102" = 0 deg
node "KASTEN_XY"
node "KASTEN_YZ"
node "KASTEN_ZX"
node "KASTEN_X"
node "KASTEN_Y"
node "KASTEN_Z"
node "KASTEN_Center"
body "Solid1"
other parameters: "d103" = 0
